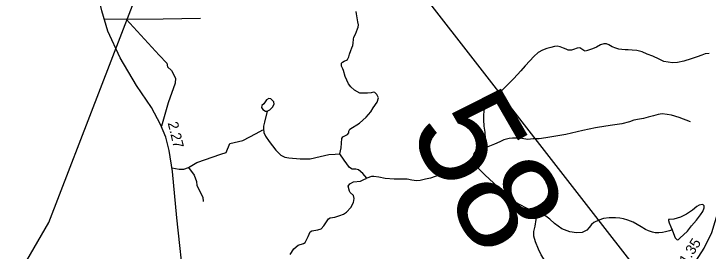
# Model space of a CAD drawing. Extents: x 2056842 to 2160602, y 826753 to 1016856.
# Drawn here: x 2087342 to 2095733, y 872332 to 875198 of the extents above; entities that cross this region are included whole.
import ezdxf

# ---------------------------------------------------------------- set-up
doc = ezdxf.new("R2010")
doc.units = 0
for name, color, linetype in [('Exist Hydrographic Creek Single Shore', 7, 'Continuous'), ('Exist Hydrographic Misc Water Feature', 7, 'Continuous'), ('Exist Road Non-System Type 51', 7, 'Continuous'), ('Exist Road Primary US Attributed', 7, 'Continuous'), ('Exist Road Primary US Mileage Hundredths English Label', 7, 'Continuous'), ('Exist Road Secondary Mileage Hundredths English Label', 7, 'Continuous'), ('Exist Road Secondary Structure Standard Bridge Number Label', 7, 'Continuous'), ('Exist Road Secondary Type 51 Attributed', 7, 'Continuous'), ('Exist Utilities Electrical Transmission Line', 7, 'Continuous'), ('Exist Utilities Telephone Line', 7, 'Continuous')]:
    doc.layers.add(name, color=color, linetype=linetype)

msp = doc.modelspace()

# ---------------------------------------------------------------- linework, layer by layer
at = {"layer": 'Exist Hydrographic Creek Single Shore'}
for points in [[(2091282.9, 873506.2), (2091296.7, 873580), (2091306.7, 873692), (2091316.7, 873714.5), (2091372.9, 873742), (2091390.4, 873759.5), (2091391.6, 873782), (2091401.6, 873805.8), (2091519.1, 873879.6), (2091600.3, 873950.8), (2091657.8, 874015.8), (2091685.2, 874062.1), (2091734, 874132.7), (2091747.7, 874184), (2091727.7, 874225.2), (2091705.2, 874247.7), (2091689, 874252.7), (2091660.3, 874244), (2091615.8, 874240.6), (2091525.3, 874241.5), (2091457.8, 874277.7), (2091416.6, 874316.5), (2091387.9, 874351.5), (2091365.4, 874398.1), (2091347.3, 874441.7), (2091325.2, 874515.7), (2091317.1, 874535.9), (2091308.9, 874551.8), (2091301, 874567.7), (2091300.7, 874587.7), (2091302.7, 874603.8), (2091314.8, 874615.7), (2091334.7, 874625.8), (2091360.8, 874638), (2091372.5, 874647.9), (2091388.6, 874678.1), (2091400.4, 874710), (2091416.5, 874757.9), (2091428.3, 874790.2), (2091438.1, 874818.2), (2091441.9, 874846), (2091445.9, 874894.1), (2091450, 874918), (2091469.7, 874952.1), (2091481.6, 874986.3), (2091495.4, 875018.1), (2091503.3, 875038.3), (2091507.5, 875066.4), (2091499.4, 875102.4), (2091483, 875198.2)], [(2091483, 875198.2), (2091479, 875226.2)], [(2095743.8, 874717.8), (2095695.9, 874715.8), (2095657.9, 874699.6), (2095602.1, 874681.2), (2095526.3, 874657), (2095438.5, 874627), (2095362.2, 874610.5), (2095302.6, 874606.6), (2095250.7, 874614.5), (2095198.4, 874622.4), (2095142.2, 874650), (2095066.3, 874685.9), (2094996, 874713.5), (2094935.7, 874739.3), (2094872.2, 874755.1), (2094816.2, 874761), (2094768, 874764.7), (2094732.3, 874764.8), (2094688.2, 874768.3), (2094651.9, 874772.6), (2094616.3, 874782.4), (2094572, 874802.1), (2094533.8, 874824.2), (2094503.7, 874836.1), (2094472.1, 874836), (2094434, 874823.9), (2094383.7, 874797.8), (2094335.7, 874777.5), (2094275.9, 874757.3), (2094248.2, 874748.9), (2094232.2, 874755.1), (2094208, 874772.9), (2094184, 874787), (2094152, 874784.6), (2094104, 874766.7), (2094080, 874760.6), (2094040.1, 874760.6), (2094016.3, 874772.4), (2093984.1, 874784.1), (2093945.9, 874802), (2093909.9, 874809.9), (2093878.1, 874805.8), (2093830.3, 874793.6), (2093782.1, 874779.9), (2093732.3, 874761.4), (2093678.4, 874731.5), (2093626.5, 874683.3), (2093578.7, 874632.9), (2093522.5, 874568.8), (2093469, 874510.7), (2093385.3, 874416.3), (2093267.8, 874299.8), (2093216, 874244), (2093144, 874181.8), (2093084.1, 874125.5), (2093032.6, 874061.2), (2093020.5, 874029.4), (2093017.1, 873965.3), (2093018.9, 873917.2), (2093021, 873841.3), (2093035.5, 873769.4), (2093037.6, 873685.5), (2093029.8, 873633.5), (2093026.1, 873585.3)], [(2090404.5, 874022.6), (2090370.8, 873891.3), (2090360.8, 873840), (2090360.8, 873811.3), (2090364.5, 873766.3), (2090382, 873720), (2090425.8, 873657.3), (2090508.5, 873553.5), (2090568.7, 873491.6), (2090616.7, 873465.7), (2090664.7, 873458), (2090801.9, 873448.7), (2090924.3, 873448.7), (2091044.3, 873475), (2091148, 873498.7), (2091225.4, 873502.5), (2091282.9, 873506.2)], [(2095520.7, 873893), (2095384.8, 873946.9), (2095288.6, 873974.4), (2095236.3, 873982.4), (2095178.3, 873990.4), (2095128.5, 873982.1), (2095072.5, 873967.9), (2095008.5, 873951.6), (2094952.7, 873935.3), (2094904.8, 873925.1), (2094836.7, 873915.2), (2094783, 873892.8), (2094690.9, 873868.6), (2094578.9, 873852.3), (2094494.9, 873839.9), (2094371.2, 873821.4), (2094219.1, 873791.2), (2094011.4, 873742.4), (2093773.5, 873699.8), (2093689.8, 873687.7), (2093617.4, 873687.2), (2093553.7, 873679), (2093481.7, 873690.8), (2093421.8, 873698.6), (2093369.5, 873696.5), (2093329.4, 873692.4), (2093265.6, 873676.1), (2093213.7, 873653.9), (2093149.5, 873625.9), (2093070, 873593.7), (2093026.1, 873585.3)], [(2091607.8, 873213.9), (2091557.8, 873271.5), (2091508.7, 873314.6), (2091474.1, 873321.2), (2091431.6, 873323.7), (2091396.6, 873341.2), (2091334.1, 873432.5), (2091282.9, 873506.2)], [(2092818.4, 873392.9), (2092802.4, 873373), (2092786.8, 873352.6), (2092764.6, 873322.7), (2092748.6, 873310.5), (2092729, 873302.6), (2092676.9, 873290.6), (2092577, 873259.8), (2092505, 873248), (2092433.1, 873231.7), (2092377.1, 873215.4), (2092317.2, 873203), (2092253.4, 873187.1), (2092209.6, 873180.9), (2092153.4, 873188.9), (2092097.2, 873200.7), (2092057.2, 873200.3), (2091937.3, 873202.2), (2091829.2, 873209.7), (2091753.3, 873225.6), (2091693.4, 873233.1), (2091665.4, 873233.3), (2091607.8, 873213.9)], [(2093656, 872803.4), (2093624, 872813.4), (2093582.2, 872829.1), (2093536, 872849.1), (2093460.2, 872892.7), (2093373.8, 872938.6), (2093295.9, 873006.4), (2093223.5, 873080.3), (2093141.1, 873153.6), (2093034.9, 873253.4), (2092942.6, 873347.3), (2092883, 873379.1), (2092851, 873381), (2092818.4, 873392.9)], [(2090679.4, 872292.4), (2090725.6, 872359.9), (2090779.4, 872402.4), (2090840.6, 872422.2), (2090861.8, 872437.2), (2090898.1, 872509.7), (2090924.3, 872563.5), (2090943.1, 872577.2), (2091015.5, 872588.5), (2091056.8, 872603.2), (2091089.2, 872635.7), (2091144.2, 872722), (2091166.7, 872735.7), (2091220.4, 872742), (2091282.9, 872762), (2091325.4, 872778.2), (2091362.9, 872803.3), (2091414.1, 872858.3), (2091447.8, 872920.8), (2091456.6, 872968.9), (2091447.8, 873002.7), (2091407.6, 873042.1), (2091399.7, 873058.3), (2091384.1, 873117.7), (2091402.9, 873145.2), (2091446.6, 873170.2), (2091531.6, 873177.7), (2091565.3, 873191.4), (2091607.8, 873213.9)], [(2095297, 872590.6), (2095266.5, 872578.7), (2095218.9, 872566.4), (2095182.8, 872558.5), (2095138.9, 872552.2), (2095094.9, 872554), (2095061, 872562), (2095011, 872575.7), (2094974.5, 872593.7), (2094922.6, 872623.5), (2094828.5, 872681.3), (2094764.5, 872705.2), (2094708.5, 872720.9), (2094664.2, 872728.8), (2094612.2, 872732.6), (2094538.5, 872736.1), (2094468.4, 872726.1), (2094412.2, 872705.8), (2094352.4, 872677.9), (2094324.1, 872652.3), (2094297.3, 872615.8), (2094266.9, 872584.2), (2094209.8, 872557.5), (2094144.2, 872553.8), (2094062.8, 872564.8), (2093965.5, 872602.5), (2093876.8, 872666.9), (2093820.9, 872718), (2093772.7, 872756), (2093656, 872803.4)]]:
    msp.add_lwpolyline(points, dxfattribs=at)
at = {"layer": 'Exist Hydrographic Misc Water Feature'}
for points in [[(2090404.5, 874022.6), (2090434.5, 874038.8), (2090467, 874071.3), (2090488.2, 874106.3), (2090484.5, 874135.1), (2090447, 874173.8), (2090424.5, 874176.3), (2090397, 874161.3), (2090364.5, 874112.6), (2090339.6, 874092.6), (2090333.3, 874068.8), (2090350.8, 874042.6), (2090384.5, 874021.3), (2090404.5, 874022.6)], [(2093026.1, 873585.3), (2093000, 873569.4), (2092972.2, 873555.4), (2092940.4, 873543.2), (2092914.1, 873528.8), (2092902.2, 873513.3), (2092894, 873477.2), (2092886.2, 873453.2), (2092876.8, 873418.9), (2092858.8, 873405), (2092818.4, 873392.9)], [(2095297, 872590.6), (2095325.4, 872514), (2095336.3, 872490.9), (2095359.4, 872470.3), (2095374, 872472.7), (2095391, 872488.5), (2095482.1, 872571.2), (2095532, 872638.1), (2095591.5, 872707.4), (2095640.2, 872769.4), (2095670.5, 872812), (2095686.3, 872855.8), (2095685.1, 872880.1), (2095671.8, 872892.3), (2095659.6, 872895.9), (2095624.3, 872886.2), (2095597.6, 872869.1), (2095545.3, 872827.8), (2095470, 872776.7), (2095399.5, 872743.9), (2095320.5, 872717.1), (2095265.8, 872712.3), (2095256.1, 872713.5), (2095252.4, 872703.8), (2095260.9, 872673.4), (2095282.8, 872627.1), (2095297, 872590.6)], [(2093972.6, 871722.3), (2093960.4, 871777.1), (2093931.2, 871886.4), (2093920.9, 871942.3), (2093908.8, 871982.2), (2093892.8, 872026.4), (2093864.7, 872066.1), (2093834.6, 872102.3), (2093802.6, 872140), (2093762.2, 872211.8), (2093715.9, 872287.9), (2093683.9, 872355.6), (2093647.4, 872443.5), (2093627.3, 872513.5), (2093627.3, 872569.5), (2093642.7, 872631.6), (2093652.7, 872715.4), (2093660.5, 872771.4), (2093656, 872803.4)]]:
    msp.add_lwpolyline(points, dxfattribs=at)
at = {"layer": 'Exist Road Non-System Type 51'}
msp.add_line((2088431.9, 875139.2), (2088699.9, 875134.7), dxfattribs=at)
for points in [[(2088699.9, 875134.7), (2089144.5, 875137), (2089595.8, 875145.6)], [(2088699.9, 875134.7), (2089098.9, 874701.2), (2089189.2, 874601.4), (2089196.8, 874557.6), (2089246.2, 874513.9), (2089295.6, 874422.6), (2089291.8, 874359.9), (2089208.2, 874122.2), (2089127.8, 873840.9)], [(2089454.3, 873342), (2089553.1, 873402.9), (2089841.9, 873501.7), (2089908.4, 873524.6), (2089950.2, 873632.9), (2090110.8, 873668.1), (2090272.3, 873753.7), (2090350.2, 873799.3)], [(2089250.9, 873336.5), (2089340.2, 873321.1), (2089395.4, 873323), (2089454.3, 873342)], [(2089454.3, 873342), (2089522.7, 873248.8), (2089549.3, 873172.8), (2089553.1, 873123.3), (2089625.3, 872984.5), (2089631, 872933.2)]]:
    msp.add_lwpolyline(points, dxfattribs=at)
at = {"layer": 'Exist Road Primary US Attributed'}
msp.add_lwpolyline([(2094179.6, 867992.5), (2094151.1, 868251.1), (2094156.8, 868467.8), (2094195.8, 868930.8), (2094230, 869299.7), (2094262.3, 869832.1), (2094306.9, 870380.7), (2094351.6, 870615.5), (2094459.9, 870896.9), (2094560.6, 871060.4), (2094700.2, 871257.2), (2095110.7, 871679.3), (2095427, 872011.1), (2095548.7, 872153.7), (2095683.6, 872366.7), (2095779.5, 872555.9), (2095872.6, 872862), (2095922, 873185.3), (2095961, 873452.4), (2095983.8, 873865), (2095966.7, 874108.4), (2095931.5, 874579)], dxfattribs=at)
at = {"layer": 'Exist Road Secondary Type 51 Attributed'}
msp.add_lwpolyline([(2089403.8, 871881.2), (2089310.7, 872736.1), (2089257.8, 873292.8), (2089217.6, 873546.2), (2089177.4, 873710.2), (2089115.6, 873863), (2089003.9, 874065.7), (2088822.1, 874334), (2088627.7, 874665.7), (2088475.8, 874989.2), (2088403.5, 875235.9), (2088339.5, 875501.2), (2088256.8, 876177.2), (2088159.2, 876823.4), (2088066.1, 877530.7), (2087947.7, 878394.6), (2087847.2, 879171.9), (2087812.9, 879416.4), (2087739.2, 879943.3), (2087696, 880266.8), (2087649, 880473.3), (2087577.5, 880646.2), (2087488.2, 880813.1), (2087343.7, 881023.3)], dxfattribs=at)
at = {"layer": 'Exist Utilities Electrical Transmission Line'}
msp.add_lwpolyline([(2090208.9, 878090.6), (2090399.6, 877911.2), (2091042.2, 877021.2), (2091166.6, 876875.7), (2095091.8, 871822.6), (2095202.4, 871658.9), (2098164.4, 867008.7), (2098184.9, 866904.8), (2098734, 864623.2), (2099022.7, 863475.6), (2099626.1, 861080), (2100400.4, 858056.5), (2100951.6, 855844.8), (2101980.8, 853661.7), (2102801.4, 851906.3), (2103296.8, 850944.6), (2103702.1, 850075), (2103840.6, 849731.1), (2105377.5, 846510.3), (2106244.1, 844636.9), (2107548.3, 841869.9), (2108761.2, 839864.8), (2109358.7, 838871.2), (2109834.3, 838086.5)], dxfattribs=at)
at = {"layer": 'Exist Utilities Telephone Line'}
msp.add_lwpolyline([(2070574.6, 855889.8), (2073540.2, 858741.1), (2079471.4, 864196.3), (2082575.1, 867047.6), (2086740, 870917.2), (2087764.9, 872677.4), (2089015.1, 875921.4), (2089705.6, 877143.4), (2092053.4, 881391.2), (2094430.2, 885697.2), (2096843.4, 888330.3), (2097766.5, 889363.1), (2100637.6, 891101.5), (2103123.5, 892599.9), (2104820.7, 893625.5), (2107244.8, 895109.3), (2108287.8, 895378.4), (2108625.8, 895633), (2109723.4, 896782.2), (2110232.2, 897204.1), (2110707.5, 898076.3)], dxfattribs=at)

# ---------------------------------------------------------------- texts
at = {"layer": 'Exist Road Primary US Mileage Hundredths English Label'}
msp.add_text('1.35', height=125, rotation=57.64583, dxfattribs=at).set_placement((2095479.1, 872160.8))
at = {"layer": 'Exist Road Secondary Mileage Hundredths English Label'}
msp.add_text('2.27', height=125, rotation=283.78207, dxfattribs=at).set_placement((2089200.1, 873880))
at = {"layer": 'Exist Road Secondary Structure Standard Bridge Number Label'}
msp.add_text('58', height=1230.31, rotation=300, dxfattribs=at).set_placement((2092094.8, 873797.3))

doc.saveas('drawing.dxf')
